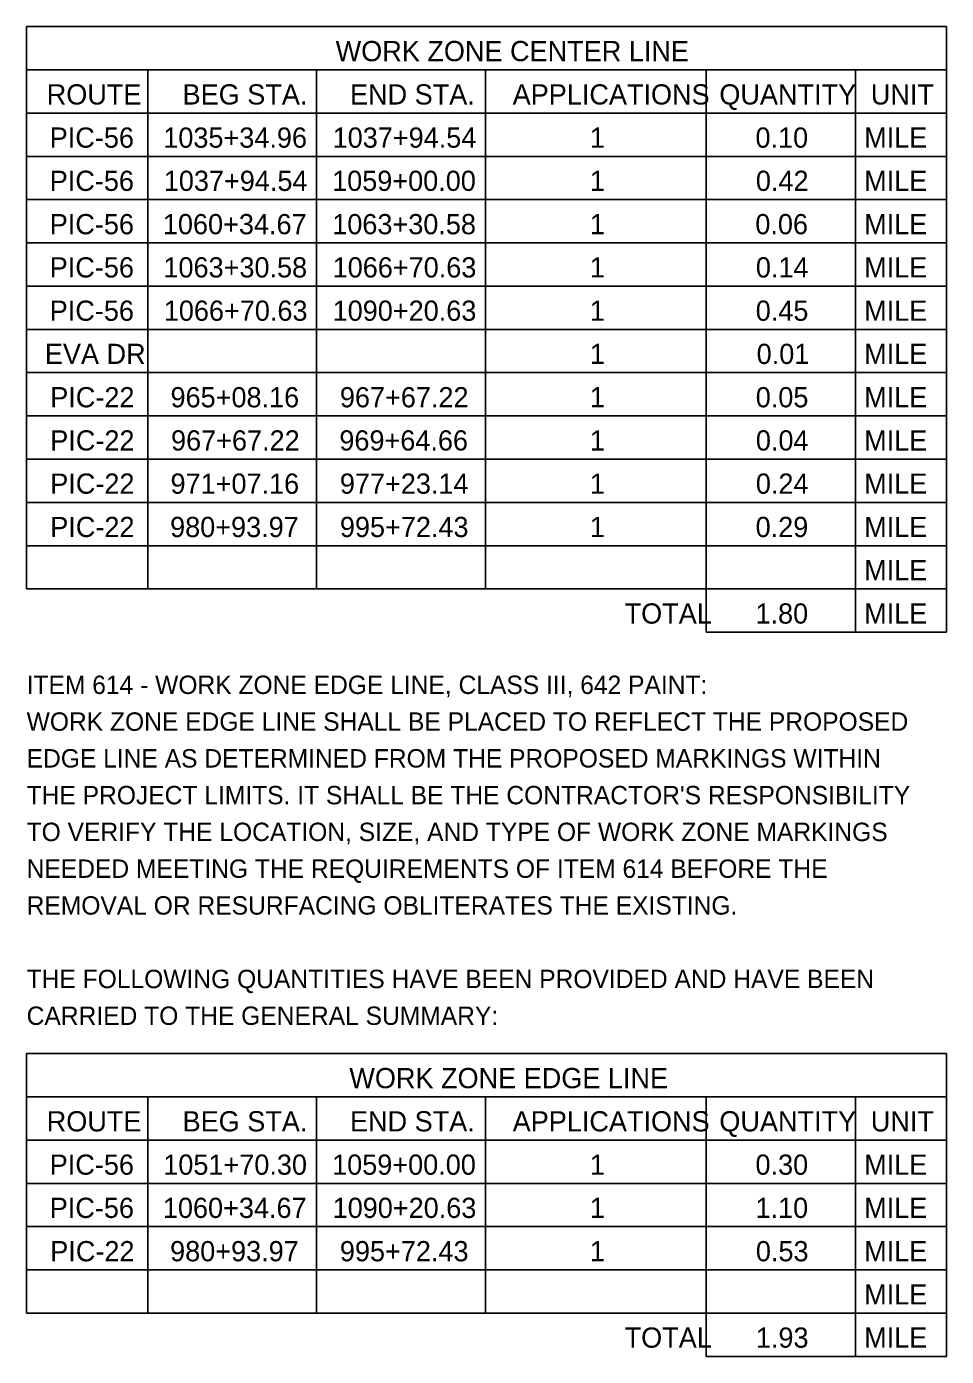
# Model space of a CAD drawing. Extents: x 0 to 37668, y -5 to 18949.
# Drawn here: x 37646.22 to 37653.22, y 18853.7 to 18863.83 of the extents above; entities that cross this region are included whole.
import ezdxf

# ---------------------------------------------------------------- set-up
doc = ezdxf.new("R2010")
doc.units = 0
doc.layers.add('SH_Data', color=7, linetype='Continuous')
doc.layers.add('SH_Text', color=7, linetype='Continuous')

msp = doc.modelspace()

# ---------------------------------------------------------------- linework, layer by layer
at = {"layer": 'SH_Data'}
for p, q in [((37646.221, 18863.825), (37653.221, 18863.825)), ((37646.221, 18863.825), (37646.221, 18859.543)), ((37653.221, 18863.825), (37653.221, 18859.214)), ((37646.221, 18863.496), (37653.221, 18863.496)), ((37647.143, 18863.496), (37647.143, 18859.543)), ((37648.428, 18863.496), (37648.428, 18859.543)), ((37649.713, 18863.496), (37649.713, 18859.543)), ((37651.393, 18863.496), (37651.393, 18859.214)), ((37652.529, 18863.496), (37652.529, 18859.214)), ((37646.221, 18863.166), (37653.221, 18863.166)), ((37646.221, 18862.837), (37653.221, 18862.837)), ((37646.221, 18862.508), (37653.221, 18862.508)), ((37646.221, 18862.178), (37653.221, 18862.178)), ((37646.221, 18861.849), (37653.221, 18861.849)), ((37646.221, 18861.519), (37653.221, 18861.519)), ((37646.221, 18861.19), (37653.221, 18861.19)), ((37646.221, 18860.861), (37653.221, 18860.861)), ((37646.221, 18860.531), (37653.221, 18860.531)), ((37646.221, 18860.202), (37653.221, 18860.202)), ((37646.221, 18859.872), (37653.221, 18859.872)), ((37646.221, 18859.543), (37653.221, 18859.543)), ((37651.393, 18859.214), (37653.221, 18859.214)), ((37646.221, 18856.005), (37653.221, 18856.005)), ((37646.221, 18856.005), (37646.221, 18854.028)), ((37653.221, 18856.005), (37653.221, 18853.699)), ((37646.221, 18855.675), (37653.221, 18855.675)), ((37647.143, 18855.675), (37647.143, 18854.028)), ((37648.428, 18855.675), (37648.428, 18854.028)), ((37649.713, 18855.675), (37649.713, 18854.028)), ((37651.393, 18855.675), (37651.393, 18853.699)), ((37652.529, 18855.675), (37652.529, 18853.699)), ((37646.221, 18855.346), (37653.221, 18855.346)), ((37646.221, 18855.016), (37653.221, 18855.016)), ((37646.221, 18854.687), (37653.221, 18854.687)), ((37646.221, 18854.358), (37653.221, 18854.358)), ((37646.221, 18854.028), (37653.221, 18854.028)), ((37651.393, 18853.699), (37653.221, 18853.699))]:
    msp.add_line(p, q, dxfattribs=at)

# ---------------------------------------------------------------- texts
for s, p in [('WORK ZONE CENTER LINE', (37648.573, 18863.562)), ('ROUTE', (37646.374, 18863.232)), ('BEG STA.', (37647.408, 18863.232)), ('END STA.', (37648.682, 18863.232)), ('APPLICATIONS', (37649.92, 18863.232)), ('QUANTITY', (37651.493, 18863.232)), ('UNIT', (37652.646, 18863.232)), ('PIC-56', (37646.397, 18862.903)), ('1035+34.96', (37647.261, 18862.903)), ('1037+94.54', (37648.55, 18862.903)), ('1', (37650.507, 18862.903)), ('0.10', (37651.768, 18862.903)), ('MILE', (37652.595, 18862.903)), ('PIC-56', (37646.397, 18862.574)), ('1037+94.54', (37647.265, 18862.574)), ('1059+00.00', (37648.546, 18862.574)), ('1', (37650.507, 18862.574)), ('0.42', (37651.771, 18862.574)), ('MILE', (37652.595, 18862.574)), ('PIC-56', (37646.397, 18862.244)), ('1060+34.67', (37647.258, 18862.244)), ('1063+30.58', (37648.547, 18862.244)), ('1', (37650.507, 18862.244)), ('0.06', (37651.767, 18862.244)), ('MILE', (37652.595, 18862.244)), ('PIC-56', (37646.397, 18861.915)), ('1063+30.58', (37647.262, 18861.915)), ('1066+70.63', (37648.55, 18861.915)), ('1', (37650.507, 18861.915)), ('0.14', (37651.771, 18861.915)), ('MILE', (37652.595, 18861.915)), ('PIC-56', (37646.397, 18861.585)), ('1066+70.63', (37647.265, 18861.585)), ('1090+20.63', (37648.55, 18861.585)), ('1', (37650.507, 18861.585)), ('0.45', (37651.77, 18861.585)), ('MILE', (37652.595, 18861.585)), ('EVA DR', (37646.36, 18861.256)), ('1', (37650.507, 18861.256)), ('0.01', (37651.777, 18861.256)), ('MILE', (37652.595, 18861.256)), ('PIC-22', (37646.401, 18860.926)), ('965+08.16', (37647.316, 18860.926)), ('967+67.22', (37648.605, 18860.926)), ('1', (37650.507, 18860.926)), ('0.05', (37651.77, 18860.926)), ('MILE', (37652.595, 18860.926)), ('PIC-22', (37646.401, 18860.597)), ('967+67.22', (37647.32, 18860.597)), ('969+64.66', (37648.601, 18860.597)), ('1', (37650.507, 18860.597)), ('0.04', (37651.771, 18860.597)), ('MILE', (37652.595, 18860.597)), ('PIC-22', (37646.401, 18860.268)), ('971+07.16', (37647.316, 18860.268)), ('977+23.14', (37648.605, 18860.268)), ('1', (37650.507, 18860.268)), ('0.24', (37651.771, 18860.268)), ('MILE', (37652.595, 18860.268)), ('PIC-22', (37646.401, 18859.938)), ('980+93.97', (37647.313, 18859.938)), ('995+72.43', (37648.605, 18859.938)), ('1', (37650.507, 18859.938)), ('0.29', (37651.769, 18859.938)), ('MILE', (37652.595, 18859.938)), ('MILE', (37652.595, 18859.609)), ('TOTAL', (37650.772, 18859.279)), ('1.80', (37651.768, 18859.279)), ('MILE', (37652.595, 18859.279)), ('WORK ZONE EDGE LINE', (37648.677, 18855.741)), ('ROUTE', (37646.374, 18855.412)), ('BEG STA.', (37647.408, 18855.412)), ('END STA.', (37648.682, 18855.412)), ('APPLICATIONS', (37649.92, 18855.412)), ('QUANTITY', (37651.493, 18855.412)), ('UNIT', (37652.646, 18855.412)), ('PIC-56', (37646.397, 18855.082)), ('1051+70.30', (37647.261, 18855.082)), ('1059+00.00', (37648.546, 18855.082)), ('1', (37650.507, 18855.082)), ('0.30', (37651.768, 18855.082)), ('MILE', (37652.595, 18855.082)), ('PIC-56', (37646.397, 18854.753)), ('1060+34.67', (37647.258, 18854.753)), ('1090+20.63', (37648.55, 18854.753)), ('1', (37650.507, 18854.753)), ('1.10', (37651.768, 18854.753)), ('MILE', (37652.595, 18854.753)), ('PIC-22', (37646.401, 18854.423)), ('980+93.97', (37647.313, 18854.423)), ('995+72.43', (37648.605, 18854.423)), ('1', (37650.507, 18854.423)), ('0.53', (37651.771, 18854.423)), ('MILE', (37652.595, 18854.423)), ('MILE', (37652.595, 18854.094)), ('TOTAL', (37650.772, 18853.765)), ('1.93', (37651.771, 18853.765)), ('MILE', (37652.595, 18853.765))]:
    msp.add_text(s, height=0.154, dxfattribs=at).set_placement(p)
at = {"layer": 'SH_Text'}
for s, p in [('ITEM 614 - WORK ZONE EDGE LINE, CLASS III, 642 PAINT:', (37646.221, 18858.743)), ('WORK ZONE EDGE LINE SHALL BE PLACED TO REFLECT THE PROPOSED ', (37646.221, 18858.463)), ('EDGE LINE AS DETERMINED FROM THE PROPOSED MARKINGS WITHIN ', (37646.221, 18858.183)), ("THE PROJECT LIMITS. IT SHALL BE THE CONTRACTOR'S RESPONSIBILITY ", (37646.221, 18857.903)), ('TO VERIFY THE LOCATION, SIZE, AND TYPE OF WORK ZONE MARKINGS ', (37646.221, 18857.623)), ('NEEDED MEETING THE REQUIREMENTS OF ITEM 614 BEFORE THE ', (37646.221, 18857.343)), ('REMOVAL OR RESURFACING OBLITERATES THE EXISTING.', (37646.221, 18857.063)), ('THE FOLLOWING QUANTITIES HAVE BEEN PROVIDED AND HAVE BEEN ', (37646.221, 18856.503)), ('CARRIED TO THE GENERAL SUMMARY:', (37646.221, 18856.223))]:
    msp.add_text(s, height=0.14, dxfattribs=at).set_placement(p)

doc.saveas('drawing.dxf')
